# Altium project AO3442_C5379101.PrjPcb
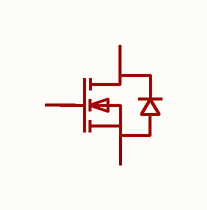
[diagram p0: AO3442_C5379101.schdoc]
1 sheet, 1 parts. Net scope: global (net labels, ports and power ports of the same name join across sheets).

## Sheet AO3442_C5379101.schdoc
size 127 x 101 mm

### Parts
Q?  ao3442_c5379101  [SOT-23-3_L2.9-W1.6-P1.90-LS2.8-BR]  (value not drawn)

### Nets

Not connected (* = marked no-connect by the designer): Q? 1(G) 2(S) 3(D)

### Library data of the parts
Q? = ao3442_c5379101: 数量:1个N沟道;漏源电压(Vdss):100V;连续漏极电流(Id):1.3A;导通电阻(RDS(on)):500mΩ@10V;耗散功率(Pd):1.56W;阈值电压(Vgs(th)):1.6V;; Manufacturer: MSKSEMI(美森科); ManufacturerPart: AO3442; AddInBom: yes; ModelId: 89cb27a44ab2466697082bb9fd73a7d0; ModelName: SOT-23-3L_L2.9-W1.6-H1.1-LS2.8-P0.95; ModelTransform: 114.173,110.236,0,90,0,0,0,0,0; Number: 1个N沟道; Drain to Source Voltage: 100V; Current - Continuous Drain(Id): 1.3A; Pd - Power Dissipation: 1.56W; Gate Threshold Voltage (Vgs(th)): 1.6V; Gate Charge(Qg): 9nC@10V; Input Capacitance(Ciss): 492pF; Reverse Transfer Capacitance (Crss@Vds): 15pF; Output Capacitance(Coss): 27pF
